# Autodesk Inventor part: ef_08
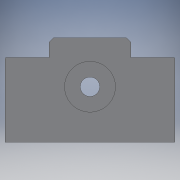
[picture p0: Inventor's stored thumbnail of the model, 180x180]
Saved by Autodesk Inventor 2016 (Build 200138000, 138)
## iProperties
Company: TraceParts S.A.
Created: 2017-01
Part Number: ef_08
Checked By: TraceParts S.A.
Catalog Web Link: www.traceparts.com
Document SubType Name: Modeling
Designer: TraceParts
Material: Типовые
Density: 1 g/cm^3
Appearance: По умолчанию
REFERENCE: EF 08
SUPPLIER: Technische Antriebselemente GmbH - Germany
DESIGN: Свободная опора EF
TraceParts.PartNumber: 80-08072009-327336
TRACEPARTS: TRACEPARTS
TraceParts.PartTitle: Свободная опора EF
TraceParts.InstanceId: 80-08072009-32733651DE4AGLKJCTO750ICCWWQRA4
TraceParts.PartLanguage: ru
TraceParts.ClassPath: TEA_GER:/TEA_GER.1/TEA.120/TEA.120.020/80-08072009-327336
TraceParts.PartVersion: 1.0.8
TraceParts.PartStatus: Published
Author: TraceParts
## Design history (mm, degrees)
feature "ef_08"
node "Твердое тело1"
node "Твердые тела"
node "Поверхностные тела"
